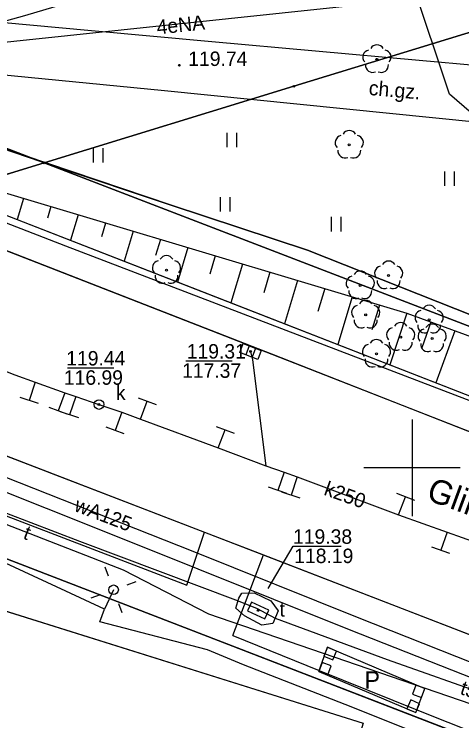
# Model space of a CAD drawing. Extents: x 6432121 to 6432331, y 5662538 to 5662686.
# Drawn here: x 6432179.34 to 6432202.58, y 5662586.88 to 5662623.53 of the extents above; entities that cross this region are included whole.
import ezdxf

# ---------------------------------------------------------------- set-up
doc = ezdxf.new("R2010")
doc.units = 0
for name, color, linetype in [('Warstwa 1', 7, 'Continuous'), ('Warstwa 10', 7, 'Continuous'), ('Warstwa 11', 7, 'Continuous'), ('Warstwa 12', 7, 'Continuous'), ('Warstwa 13', 7, 'Continuous'), ('Warstwa 14', 7, 'Continuous'), ('Warstwa 15', 7, 'Continuous'), ('Warstwa 16', 7, 'Continuous'), ('Warstwa 19', 7, 'Continuous'), ('Warstwa 2', 7, 'Continuous'), ('Warstwa 20', 7, 'Continuous'), ('Warstwa 21', 7, 'Continuous'), ('Warstwa 25', 7, 'Continuous'), ('Warstwa 34', 7, 'Continuous'), ('Warstwa 4', 7, 'Continuous'), ('Warstwa 5', 7, 'Continuous'), ('Warstwa 6', 7, 'Continuous'), ('Warstwa 63', 7, 'Continuous'), ('Warstwa 8', 7, 'Continuous'), ('Warstwa 9', 7, 'Continuous')]:
    doc.layers.add(name, color=color, linetype=linetype)

msp = doc.modelspace()

# ---------------------------------------------------------------- linework, layer by layer
at = {"layer": 'Warstwa 1'}
for p, q in [((6432193.86, 5662619.79), (6432228.29, 5662630.34)), ((6432193.86, 5662619.79), (6432228.29, 5662630.34)), ((6432164.332, 5662622.19), (6432180.9, 5662615.82)), ((6432164.332, 5662622.19), (6432180.9, 5662615.82)), ((6432180.9, 5662615.82), (6432193.86, 5662619.79)), ((6432180.9, 5662615.82), (6432193.86, 5662619.79)), ((6432147.05, 5662605.45), (6432180.9, 5662615.82)), ((6432147.05, 5662605.45), (6432180.9, 5662615.82)), ((6432180.9, 5662615.82), (6432259.074, 5662585.787)), ((6432180.9, 5662615.82), (6432259.074, 5662585.787)), ((6432155.186, 5662604.45), (6432246.621, 5662569.177)), ((6432155.186, 5662604.45), (6432246.621, 5662569.177))]:
    msp.add_line(p, q, dxfattribs=at)
msp.add_lwpolyline([(6432127.995, 5662556.053), (6432141.94, 5662600.47), (6432146.84, 5662598.95), (6432146.23, 5662597.05), (6432150.06, 5662595.86), (6432151.74, 5662601.09), (6432197.45, 5662586.76), (6432193.11, 5662572.86), (6432152.51, 5662585.63), (6432148.5, 5662572.83), (6432147.6, 5662573.08), (6432145.6, 5662566.71), (6432142.254, 5662556.053)], dxfattribs=at)
at = {"layer": 'Warstwa 10'}
for p, q in [((6432167.648, 5662617.501), (6432210.732, 5662600.706)), ((6432174.135, 5662615.678), (6432199.73, 5662608.02)), ((6432179.823, 5662613.976), (6432179.495, 5662612.883)), ((6432181.245, 5662613.551), (6432181.064, 5662612.947)), ((6432182.666, 5662613.125), (6432182.27, 5662611.801)), ((6432184.088, 5662612.7), (6432183.873, 5662611.98)), ((6432185.51, 5662612.275), (6432185.044, 5662610.719)), ((6432186.932, 5662611.849), (6432186.683, 5662611.014)), ((6432188.355, 5662611.423), (6432187.82, 5662609.638)), ((6432189.777, 5662610.998), (6432189.492, 5662610.047)), ((6432191.199, 5662610.573), (6432190.594, 5662608.556)), ((6432192.621, 5662610.147), (6432192.302, 5662609.081)), ((6432194.043, 5662609.722), (6432193.369, 5662607.474)), ((6432195.464, 5662609.297), (6432195.11, 5662608.115)), ((6432196.886, 5662608.87), (6432196.144, 5662606.392)), ((6432198.308, 5662608.445), (6432197.901, 5662607.156)), ((6432199.73, 5662608.02), (6432198.84, 5662605.342)), ((6432199.73, 5662608.02), (6432207.218, 5662605.272)), ((6432200.978, 5662607.562), (6432200.508, 5662606.218)), ((6432202.226, 5662607.103), (6432201.236, 5662604.407))]:
    msp.add_line(p, q, dxfattribs=at)
at = {"layer": 'Warstwa 11'}
for centre in [(6432198.173, 5662621.189), (6432196.737, 5662616.75), (6432187.249, 5662610.257), (6432198.78, 5662609.976), (6432197.308, 5662609.459), (6432197.589, 5662607.938), (6432200.883, 5662607.681), (6432199.407, 5662606.781), (6432201.038, 5662606.711), (6432198.147, 5662605.911)]:
    msp.add_circle(centre, 0.05, dxfattribs=at)
for centre, start, end in [((6432198.173, 5662621.564), 30.1471, 149.8529), ((6432197.816, 5662621.305), 102.1471, 221.8529), ((6432198.53, 5662621.305), 318.1471, 77.8529), ((6432197.953, 5662620.886), 174.1471, 293.8529), ((6432198.393, 5662620.886), 246.1471, 5.8529), ((6432196.38, 5662616.866), 102.1471, 221.8529), ((6432196.737, 5662617.125), 30.1471, 149.8529), ((6432197.094, 5662616.866), 318.1471, 77.8529), ((6432196.517, 5662616.447), 174.1471, 293.8529), ((6432196.957, 5662616.447), 246.1471, 5.8529), ((6432187.249, 5662610.632), 30.1471, 149.8529), ((6432186.892, 5662610.373), 102.1471, 221.8529), ((6432187.606, 5662610.373), 318.1471, 77.8529), ((6432198.78, 5662610.351), 30.1471, 149.8529), ((6432197.308, 5662609.834), 30.1471, 149.8529), ((6432198.423, 5662610.092), 102.1471, 221.8529), ((6432199.137, 5662610.092), 318.1471, 77.8529), ((6432187.029, 5662609.954), 174.1471, 293.8529), ((6432187.469, 5662609.954), 246.1471, 5.8529), ((6432196.951, 5662609.575), 102.1471, 221.8529), ((6432197.665, 5662609.575), 318.1471, 77.8529), ((6432198.56, 5662609.673), 174.1471, 293.8529), ((6432199, 5662609.673), 246.1471, 5.8529), ((6432197.088, 5662609.156), 174.1471, 293.8529), ((6432197.528, 5662609.156), 246.1471, 5.8529), ((6432197.232, 5662608.054), 102.1471, 221.8529), ((6432197.589, 5662608.313), 30.1471, 149.8529), ((6432197.946, 5662608.054), 318.1471, 77.8529), ((6432200.883, 5662608.056), 30.1471, 149.8529), ((6432200.526, 5662607.797), 102.1471, 221.8529), ((6432201.24, 5662607.797), 318.1471, 77.8529), ((6432197.369, 5662607.635), 174.1471, 293.8529), ((6432197.809, 5662607.635), 246.1471, 5.8529), ((6432199.05, 5662606.897), 102.1471, 221.8529), ((6432199.407, 5662607.156), 30.1471, 149.8529), ((6432199.764, 5662606.897), 318.1471, 77.8529), ((6432200.663, 5662607.378), 174.1471, 293.8529), ((6432201.038, 5662607.086), 30.1471, 149.8529), ((6432201.103, 5662607.378), 246.1471, 5.8529), ((6432200.681, 5662606.827), 102.1471, 221.8529), ((6432201.395, 5662606.827), 318.1471, 77.8529), ((6432198.147, 5662606.286), 30.1471, 149.8529), ((6432197.79, 5662606.027), 102.1471, 221.8529), ((6432198.504, 5662606.027), 318.1471, 77.8529), ((6432199.187, 5662606.478), 174.1471, 293.8529), ((6432199.627, 5662606.478), 246.1471, 5.8529), ((6432200.818, 5662606.408), 174.1471, 293.8529), ((6432201.258, 5662606.408), 246.1471, 5.8529), ((6432197.927, 5662605.608), 174.1471, 293.8529), ((6432198.367, 5662605.608), 246.1471, 5.8529)]:
    msp.add_arc(centre, 0.375, start, end, dxfattribs=at)
at = {"layer": 'Warstwa 12'}
for points in [[(6432248.82, 5662629.93), (6432248.54, 5662629.72), (6432247.48, 5662630.2), (6432247.186, 5662630.33), (6432247.012, 5662630.407), (6432246.73, 5662630.84), (6432246.374, 5662630.582), (6432219.55, 5662620.66), (6432213.49, 5662610.33), (6432213.18, 5662609.798), (6432212.84, 5662609.97), (6432201.94, 5662619.39), (6432188.48, 5662659.63), (6432188.372, 5662660.264), (6432188.26, 5662660.96), (6432187.54, 5662663.58), (6432189.456, 5662664.144), (6432190.073, 5662664.038), (6432190.591, 5662664.478), (6432199.77, 5662667.18), (6432202.78, 5662668.86), (6432236.07, 5662677.73), (6432238.751, 5662681.053)], [(6432151.934, 5662659.962), (6432163.647, 5662662.364), (6432165.031, 5662661.271), (6432166.026, 5662656.887), (6432167.998, 5662648.227), (6432170.198, 5662638.637), (6432172.215, 5662629.789), (6432174.2, 5662621.336), (6432174.764, 5662618.709), (6432176.004, 5662617.499), (6432181.388, 5662615.664), (6432187.493, 5662613.63), (6432194.563, 5662611.29), (6432209.024, 5662605.561), (6432218.668, 5662601.72), (6432230.17, 5662597.186), (6432236.4, 5662594.702), (6432238.551, 5662593.742), (6432242.89, 5662591.993), (6432244.915, 5662591.158), (6432249.823, 5662589.199), (6432255.518, 5662586.99), (6432264.175, 5662583.483)], [(6432156.818, 5662630.202), (6432158.039, 5662625.384), (6432159.105, 5662620.911), (6432168.554, 5662616.714), (6432182.01, 5662611.519), (6432201.034, 5662604.23), (6432217.284, 5662598.028), (6432236.124, 5662590.737), (6432242.639, 5662588.267), (6432252.12, 5662584.559), (6432258.988, 5662581.806), (6432263.17, 5662580.184), (6432269.496, 5662577.686)], [(6432244.915, 5662591.158), (6432242.89, 5662591.993), (6432238.551, 5662593.742), (6432237.475, 5662594.222), (6432236.4, 5662594.702), (6432230.17, 5662597.186), (6432224.419, 5662599.453), (6432218.668, 5662601.72), (6432209.024, 5662605.561), (6432194.563, 5662611.29), (6432187.493, 5662613.63), (6432176.004, 5662617.499), (6432174.764, 5662618.709), (6432174.2, 5662621.336), (6432172.215, 5662629.789)], [(6432249.05, 5662629.25), (6432248.64, 5662629.45), (6432162.596, 5662620.344), (6432161.76, 5662619.96)], [(6432210.104, 5662582.327), (6432202.024, 5662585.528), (6432196.52, 5662587.717), (6432191.249, 5662589.791), (6432189.37, 5662590.565), (6432183.794, 5662592.014), (6432184.035, 5662592.662), (6432182.021, 5662593.597), (6432173.569, 5662597.514), (6432171.087, 5662598.578), (6432164.548, 5662601.548), (6432162.154, 5662602.662), (6432161.25, 5662603.009), (6432157.524, 5662604.493), (6432155.401, 5662604.519), (6432154.521, 5662606.358), (6432156.966, 5662612.242), (6432159.458, 5662618.215), (6432160.518, 5662620.909), (6432160.428, 5662620.978), (6432157.66, 5662622.108), (6432158.701, 5662622.869), (6432165.926, 5662625.245)], [(6432127.185, 5662618.897), (6432135.629, 5662615.848), (6432142.79, 5662613.281), (6432154.997, 5662608.849), (6432160.46, 5662606.879), (6432165.736, 5662604.745), (6432167.852, 5662603.89), (6432175.869, 5662600.716), (6432188.607, 5662595.673), (6432197.141, 5662592.258), (6432208.285, 5662587.853), (6432217.328, 5662584.25), (6432226.269, 5662580.703), (6432229.116, 5662579.575), (6432234.631, 5662577.404), (6432234.076, 5662575.247), (6432232.817, 5662570.334), (6432230.472, 5662561.671), (6432228.926, 5662556.053)], [(6432228.367, 5662556.053), (6432231.658, 5662568.249), (6432233.96, 5662576.659), (6432221.597, 5662581.652), (6432210.31, 5662586.256), (6432196.752, 5662591.605), (6432184.96, 5662596.314), (6432169.081, 5662602.651), (6432160.264, 5662606.196), (6432148.936, 5662610.33), (6432147.827, 5662610.792), (6432135.842, 5662615.166), (6432127.959, 5662618.065)], [(6432127.946, 5662615.962), (6432128.842, 5662616.521), (6432129.879, 5662616.161), (6432135.004, 5662614.244), (6432137.96, 5662613.1), (6432142.879, 5662611.278), (6432154.141, 5662607.021), (6432159.281, 5662605.095), (6432161.845, 5662604.079), (6432162.876, 5662603.668), (6432169.279, 5662601.311), (6432171.448, 5662600.465), (6432177.657, 5662598.132), (6432182.74, 5662596.197), (6432190.963, 5662593.097), (6432191.954, 5662592.706)], [(6432125.976, 5662559.881), (6432127.22, 5662563.81), (6432133.93, 5662584.09), (6432142.61, 5662608.19), (6432143.204, 5662608.85), (6432144.41, 5662608.72), (6432156.66, 5662605.17), (6432161.55, 5662603.82), (6432185, 5662594.71), (6432189.43, 5662592.42), (6432210.16, 5662585.32), (6432215.53, 5662583.54), (6432216.154, 5662583.288)], [(6432176.128, 5662605.986), (6432178.129, 5662605.31), (6432179.366, 5662604.816), (6432180.433, 5662604.439), (6432181.97, 5662603.896), (6432182.541, 5662603.695), (6432183.741, 5662603.284), (6432184.926, 5662602.88), (6432185.896, 5662602.523), (6432189.937, 5662601.037), (6432192.41, 5662600.108)], [(6432191.614, 5662606.037), (6432191.706, 5662605.598), (6432192.41, 5662600.108)], [(6432192.41, 5662600.108), (6432193.356, 5662599.773), (6432194.036, 5662599.529), (6432199.301, 5662597.568), (6432201.822, 5662596.668), (6432203.384, 5662596.11), (6432203.955, 5662595.903), (6432205.017, 5662595.511), (6432207.109, 5662594.725), (6432209.534, 5662593.848), (6432212.881, 5662592.563), (6432213.507, 5662592.335), (6432214.063, 5662592.136), (6432214.654, 5662591.921), (6432216.043, 5662591.407), (6432218.372, 5662590.563)], [(6432184.499, 5662593.674), (6432184.035, 5662592.662)], [(6432191.954, 5662592.706), (6432192.888, 5662592.203), (6432198.702, 5662590.052), (6432204.186, 5662588.123), (6432211.524, 5662585.445), (6432215.512, 5662583.99), (6432216.154, 5662583.288)]]:
    msp.add_lwpolyline(points, dxfattribs=at)
for centre in [(6432193.86, 5662619.79), (6432180.9, 5662615.82)]:
    msp.add_circle(centre, 0.045, dxfattribs=at)
at = {"layer": 'Warstwa 14'}
for p, q in [((6432188.246, 5662605.544), (6432190.652, 5662605.544)), ((6432182.11, 5662605.184), (6432184.51, 5662605.184))]:
    msp.add_line(p, q, dxfattribs=at)
msp.add_lwpolyline([(6432192.534, 5662593.742), (6432193.823, 5662595.935), (6432196.313, 5662595.935)], dxfattribs=at)
for centre in [(6432191.614, 5662606.037), (6432191.614, 5662606.037), (6432183.741, 5662603.284), (6432183.741, 5662603.284), (6432192.007, 5662592.605), (6432192.007, 5662592.605)]:
    msp.add_circle(centre, 0.045, dxfattribs=at)
at = {"layer": 'Warstwa 16'}
msp.add_lwpolyline([(6432191.158, 5662593.497), (6432191.8, 5662593.512), (6432192.665, 5662593.101), (6432193.048, 5662592.592), (6432192.776, 5662591.931), (6432192.203, 5662591.846), (6432191.305, 5662592.327), (6432190.84, 5662592.722), (6432191.007, 5662593.236)], close=True, dxfattribs=at)
at = {"layer": 'Warstwa 19'}
for p, q in [((6432180.433, 5662604.439), (6432180.12, 5662603.489)), ((6432180.595, 5662603.333), (6432179.645, 5662603.646)), ((6432181.97, 5662603.896), (6432181.618, 5662602.96)), ((6432182.541, 5662603.695), (6432182.219, 5662602.748)), ((6432185.774, 5662603.634), (6432186.712, 5662603.288)), ((6432185.896, 5662602.523), (6432186.243, 5662603.461)), ((6432182.086, 5662602.784), (6432181.15, 5662603.136)), ((6432182.693, 5662602.587), (6432181.746, 5662602.909)), ((6432184.926, 5662602.88), (6432184.582, 5662601.941)), ((6432189.819, 5662602.149), (6432190.755, 5662601.799)), ((6432185.051, 5662601.769), (6432184.112, 5662602.113)), ((6432189.937, 5662601.037), (6432190.287, 5662601.974)), ((6432193.356, 5662599.773), (6432193.022, 5662598.831)), ((6432194.036, 5662599.529), (6432193.717, 5662598.581)), ((6432193.493, 5662598.663), (6432192.55, 5662598.998)), ((6432194.191, 5662598.422), (6432193.243, 5662598.741)), ((6432199.191, 5662598.681), (6432200.125, 5662598.324)), ((6432199.301, 5662597.568), (6432199.658, 5662598.502)), ((6432201.822, 5662596.668), (6432201.487, 5662595.726)), ((6432201.958, 5662595.558), (6432201.016, 5662595.893))]:
    msp.add_line(p, q, dxfattribs=at)
at = {"layer": 'Warstwa 2'}
msp.add_circle((6432184.499, 5662593.674), 0.25, dxfattribs=at)
at = {"layer": 'Warstwa 20'}
for p, q in [((6432174.135, 5662615.678), (6432199.73, 5662608.02)), ((6432199.73, 5662608.02), (6432207.218, 5662605.272))]:
    msp.add_line(p, q, dxfattribs=at)
at = {"layer": 'Warstwa 21'}
msp.add_line((6432167.648, 5662617.501), (6432210.732, 5662600.706), dxfattribs=at)
at = {"layer": 'Warstwa 25'}
msp.add_circle((6432187.917, 5662620.883), 0.045, dxfattribs=at)
at = {"layer": 'Warstwa 34'}
for p, q in [((6432195.149, 5662589.441), (6432195.612, 5662590.691)), ((6432195.612, 5662590.691), (6432200.657, 5662588.552)), ((6432195.149, 5662589.441), (6432200.194, 5662587.303)), ((6432200.194, 5662587.303), (6432200.657, 5662588.552))]:
    msp.add_line(p, q, dxfattribs=at)
for points in [[(6432195.417, 5662590.23), (6432195.878, 5662590.035), (6432196.073, 5662590.496), (6432195.612, 5662590.691), (6432195.417, 5662590.23)], [(6432195.618, 5662589.268), (6432195.791, 5662589.737), (6432195.322, 5662589.91), (6432195.149, 5662589.441), (6432195.618, 5662589.268)], [(6432200.188, 5662588.725), (6432200.015, 5662588.256), (6432200.484, 5662588.083), (6432200.657, 5662588.552), (6432200.188, 5662588.725)], [(6432200.389, 5662587.764), (6432199.928, 5662587.959), (6432199.733, 5662587.498), (6432200.194, 5662587.303), (6432200.389, 5662587.764)]]:
    msp.add_lwpolyline(points, dxfattribs=at)
at = {"layer": 'Warstwa 4'}
for p, q in [((6432191.539, 5662606.333), (6432191.362, 5662605.865)), ((6432191.866, 5662606.209), (6432191.689, 5662605.741))]:
    msp.add_line(p, q, dxfattribs=at)
for points in [[(6432191.235, 5662606.448), (6432192.17, 5662606.093), (6432191.993, 5662605.626), (6432191.058, 5662605.981)], [(6432192.566, 5662592.624), (6432191.657, 5662593.041), (6432191.448, 5662592.586), (6432192.357, 5662592.169)]]:
    msp.add_lwpolyline(points, close=True, dxfattribs=at)
for points in [[(6432127.995, 5662556.053), (6432141.94, 5662600.47), (6432146.84, 5662598.95), (6432146.23, 5662597.05), (6432150.06, 5662595.86), (6432151.74, 5662601.09), (6432197.45, 5662586.76), (6432193.11, 5662572.86), (6432152.51, 5662585.63), (6432148.5, 5662572.83), (6432147.6, 5662573.08), (6432142.254, 5662556.053)], [(6432184.238, 5662594.377), (6432184.064, 5662594.846)], [(6432185.202, 5662593.935), (6432185.671, 5662594.109)], [(6432183.796, 5662593.413), (6432183.327, 5662593.239)], [(6432184.76, 5662592.971), (6432184.934, 5662592.502)]]:
    msp.add_lwpolyline(points, dxfattribs=at)
msp.add_circle((6432183.741, 5662603.284), 0.25, dxfattribs=at)
at = {"layer": 'Warstwa 5'}
for p, q in [((6432179.89, 5662623.47), (6432198.46, 5662628.97)), ((6432178.65, 5662623.11), (6432179.89, 5662623.47)), ((6432178.65, 5662623.11), (6432183.354, 5662622.679)), ((6432183.354, 5662622.679), (6432189.604, 5662622.108)), ((6432189.604, 5662622.108), (6432200.367, 5662621.152)), ((6432200.367, 5662621.152), (6432206.803, 5662620.569)), ((6432175.954, 5662620.673), (6432187.151, 5662619.575)), ((6432187.151, 5662619.575), (6432213.408, 5662616.935)), ((6432190.4, 5662616.627), (6432190.4, 5662617.377)), ((6432190.9, 5662616.627), (6432190.9, 5662617.377)), ((6432183.457, 5662615.838), (6432183.457, 5662616.588)), ((6432183.957, 5662615.838), (6432183.957, 5662616.588)), ((6432174.135, 5662615.678), (6432199.73, 5662608.02)), ((6432201.695, 5662614.626), (6432201.695, 5662615.376)), ((6432202.195, 5662614.626), (6432202.195, 5662615.376)), ((6432190.047, 5662613.297), (6432190.047, 5662614.047)), ((6432190.547, 5662613.297), (6432190.547, 5662614.047)), ((6432195.817, 5662612.265), (6432195.817, 5662613.015)), ((6432196.317, 5662612.265), (6432196.317, 5662613.015)), ((6432199.73, 5662608.02), (6432207.218, 5662605.272)), ((6432164.068, 5662603.207), (6432188.299, 5662593.907)), ((6432151.991, 5662601.011), (6432197.45, 5662586.76)), ((6432188.299, 5662593.907), (6432189.213, 5662596.666)), ((6432189.213, 5662596.666), (6432192.281, 5662595.483)), ((6432190.688, 5662591.298), (6432192.281, 5662595.483)), ((6432190.688, 5662591.298), (6432195.169, 5662589.495)), ((6432195.149, 5662589.441), (6432195.169, 5662589.495)), ((6432195.149, 5662589.441), (6432200.194, 5662587.303)), ((6432200.194, 5662587.303), (6432200.249, 5662587.452)), ((6432200.249, 5662587.452), (6432209.248, 5662583.832))]:
    msp.add_line(p, q, dxfattribs=at)
at = {"layer": 'Warstwa 6'}
for points in [[(6432166.394, 5662623.975), (6432164.332, 5662622.19), (6432180.9, 5662615.82), (6432193.86, 5662619.79), (6432228.29, 5662630.34), (6432246.69, 5662636.13), (6432245.39, 5662639.916), (6432234.842, 5662644.244)], [(6432259.074, 5662585.787), (6432263.163, 5662588.197), (6432246.69, 5662636.13), (6432228.29, 5662630.34), (6432193.86, 5662619.79), (6432180.9, 5662615.82)], [(6432164.332, 5662622.19), (6432147.05, 5662605.45), (6432180.9, 5662615.82)], [(6432180.9, 5662615.82), (6432147.05, 5662605.45), (6432141.907, 5662600.47), (6432155.186, 5662604.45), (6432246.621, 5662569.177), (6432269.007, 5662560.534), (6432263.163, 5662588.197), (6432259.074, 5662585.787)]]:
    msp.add_lwpolyline(points, close=True, dxfattribs=at)
for points in [[(6432261.892, 5662579.254), (6432260.419, 5662579.482), (6432250.699, 5662583.246), (6432245.014, 5662585.481), (6432215.968, 5662596.774), (6432192.716, 5662605.904), (6432163.326, 5662617.343), (6432161.597, 5662617.988)], [(6432159.72, 5662608.085), (6432174.611, 5662602.284), (6432189.213, 5662596.666), (6432233.139, 5662579.721)], [(6432249.006, 5662556.053), (6432246.621, 5662569.177), (6432155.186, 5662604.45), (6432141.907, 5662600.47), (6432128.788, 5662558.646), (6432132.46, 5662567.032), (6432163.983, 5662578.631), (6432172.647, 5662574.865), (6432180.454, 5662556.053)]]:
    msp.add_lwpolyline(points, dxfattribs=at)
at = {"layer": 'Warstwa 63'}
for p, q in [((6432200, 5662602.5), (6432200, 5662597.5)), ((6432202.5, 5662600), (6432197.5, 5662600))]:
    msp.add_line(p, q, dxfattribs=at)
at = {"layer": 'Warstwa 8'}
for p, q in [((6432163.326, 5662617.343), (6432192.716, 5662605.904)), ((6432192.716, 5662605.904), (6432215.968, 5662596.774)), ((6432174.611, 5662602.284), (6432189.213, 5662596.666)), ((6432189.213, 5662596.666), (6432192.281, 5662595.483)), ((6432192.281, 5662595.483), (6432233.139, 5662579.721))]:
    msp.add_line(p, q, dxfattribs=at)
at = {"layer": 'Warstwa 9'}
for p, q in [((6432179.89, 5662623.47), (6432198.46, 5662628.97)), ((6432178.65, 5662623.11), (6432179.89, 5662623.47)), ((6432178.65, 5662623.11), (6432183.354, 5662622.679)), ((6432183.354, 5662622.679), (6432189.604, 5662622.108)), ((6432189.604, 5662622.108), (6432200.367, 5662621.152)), ((6432200.367, 5662621.152), (6432206.803, 5662620.569)), ((6432175.954, 5662620.673), (6432187.151, 5662619.575)), ((6432187.151, 5662619.575), (6432213.408, 5662616.935)), ((6432167.414, 5662617.592), (6432189.19, 5662609.104)), ((6432166.761, 5662616.006), (6432192.716, 5662605.904)), ((6432189.19, 5662609.104), (6432210.732, 5662600.706)), ((6432192.716, 5662605.904), (6432215.968, 5662596.774)), ((6432164.068, 5662603.207), (6432188.299, 5662593.907)), ((6432174.611, 5662602.284), (6432189.213, 5662596.666)), ((6432188.299, 5662593.907), (6432189.213, 5662596.666)), ((6432190.688, 5662591.298), (6432192.281, 5662595.483)), ((6432192.281, 5662595.483), (6432233.139, 5662579.721)), ((6432190.688, 5662591.298), (6432195.169, 5662589.495)), ((6432195.169, 5662589.495), (6432200.249, 5662587.452)), ((6432200.249, 5662587.452), (6432209.248, 5662583.832))]:
    msp.add_line(p, q, dxfattribs=at)

# ---------------------------------------------------------------- texts
at = {"layer": 'Warstwa 13'}
for s, rotation, p in [('4eNA', 6.039, (6432186.776, 5662622.478)), ('k250', 340.2682, (6432195.373, 5662598.616)), ('wA125', 339.0993, (6432182.409, 5662597.781)), ('t', 338.767, (6432179.76, 5662596.343)), ('t5', 341.3167, (6432202.445, 5662588.279))]:
    msp.add_text(s, height=0.75, rotation=rotation, dxfattribs=at).set_placement(p)
at = {"layer": 'Warstwa 14'}
for s, p in [('117.37', (6432188.056, 5662604.669)), ('116.99', (6432181.92, 5662604.309)), ('118.19', (6432193.881, 5662595.06))]:
    msp.add_text(s, height=0.75, dxfattribs=at).set_placement(p)
msp.add_text('Gliniana', height=1.25, rotation=339.8041, dxfattribs=at).set_placement((6432200.68, 5662598.367))
at = {"layer": 'Warstwa 15'}
for s, p in [('119.31', (6432188.299, 5662605.669)), ('119.44', (6432182.045, 5662605.309)), ('119.38', (6432193.817, 5662596.06))]:
    msp.add_text(s, height=0.75, dxfattribs=at).set_placement(p)
at = {"layer": 'Warstwa 25'}
msp.add_text('119.74', height=0.75, dxfattribs=at).set_placement((6432188.379, 5662620.845))
at = {"layer": 'Warstwa 34'}
msp.add_text('P', height=0.9, dxfattribs=at).set_placement((6432197.531, 5662588.547))
at = {"layer": 'Warstwa 5'}
for s, p in [('k', (6432184.621, 5662603.522)), ('t', (6432193.118, 5662592.286))]:
    msp.add_text(s, height=0.75, dxfattribs=at).set_placement(p)
at = {"layer": 'Warstwa 9'}
msp.add_text('ch.gz.', height=0.75, rotation=354.9244, dxfattribs=at).set_placement((6432197.729, 5662619.345))

doc.saveas('drawing.dxf')
